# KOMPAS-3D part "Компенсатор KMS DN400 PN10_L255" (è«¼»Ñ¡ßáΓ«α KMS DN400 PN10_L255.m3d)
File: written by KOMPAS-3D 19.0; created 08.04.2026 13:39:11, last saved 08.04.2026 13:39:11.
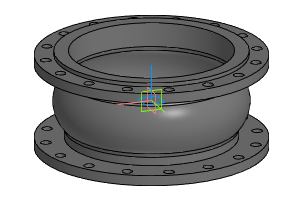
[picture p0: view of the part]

Document properties: Автор: Энергия; Полное имя файла: Z:\3.Личные\kachalov\3d для проектировщиков\7.1 Компенсатор\stp_Компенсатор KSM\Компенсатор KMS DN400 PN10_L255.m3d

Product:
- Part/product: Компенсатор KMS DN400 PN10_L255

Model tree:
1. Операция без истории:1  (labels: Компенсатор KMS DN400 PN10_L255)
